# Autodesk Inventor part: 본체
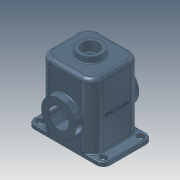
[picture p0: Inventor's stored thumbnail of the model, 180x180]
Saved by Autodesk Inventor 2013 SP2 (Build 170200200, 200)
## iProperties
Company: 한국ATC센터
Created: 2014-10
Part Number: 본체
Document SubType Name: Modeling
Designer: 한국ATC센터
Density: 2.71 g/cm^3
Material: 알루미늄 6061
Mass: 3285.46 g
Surface Area: 2358.48 cm^2
Volume: 1212.35 cm^3
Author: KYOUNG IL JANG
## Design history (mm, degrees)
sketch "스케치1"
  geometry: L1 (-70, 65)-(70, 65); L2 (70, 65)-(70, -65); L3 (70, -65)-(-70, -65); L4 (-70, -65)-(-70, 65); 3 further points
  constraints: 8 end point, 2 midpoint, 2 parallel, 1 horizontal, 1 horizontal alignment, 1 perpendicular, 1 vertical alignment
  dimensions: "d0" = 140 distance of L2.end L3.end; "d68" = 130 distance of L3.end L1.start
extrude "돌출1" new body sketch "스케치1" distance "d1" = 180; taper "d2" = 0 deg
fillet "모깎기1" dims "d3" = 20
feature "쉘1" dims "d4" = 10
sketch "스케치2"
  geometry: L1 (-70, 45)-(-70, -45) reference; L2 (-50, -65)-(-82, -65); L3 (-82, 65)-(-50, 65); L4 (-85, 57)-(-82, 57); L5 (-82, 41)-(-85, 41); L6 (-100, 47)-(-100, -47); A1 r 20 centre (-50, 45) between (-50, 65) and (-70, 45) reference; A2 r 20 centre (-50, -45) between (-70, -45) and (-50, -65) reference; A3 r 8 centre (-82, 49) between (-82, 41) and (-82, 57); A4 r 8 centre (-85, 49) between (-85, 57) and (-85, 41); A5 r 18 centre (-82, 47) between (-82, 65) and (-100, 47); A6 r 18 centre (-82, -47) between (-100, -47) and (-82, -65); 1 further point
  constraints: 10 end point, 9 tangent, 8 point on circle, 4 centre point, 2 parallel, 2 perpendicular, 1 equal radius
  dimensions: "d6" = 49 vertical distance of point (0, 0) A3.centre; "d8" = 16 distance between parallel lines of L4 L5; "d64" = 18 radius of A5; "d65" = 12 distance from line of A3.centre L1; "d66" = 30 distance between parallel lines of L6 L1; "d67" = 3 distance of A4.centre A3.centre
extrude "돌출2" join sketch "스케치2" distance "d9" = 10; taper "d10" = 0 deg
extrude "돌출3" cut sketch "스케치2" stored distance "d11" = 10; taper "d12" = 0 deg
sketch "스케치3"
  geometry: L1 (-65, 0)-(-65, 180) reference; L2 (-55, 0)-(-55, 170) reference; L3 (-83, 75)-(-51, 75); L4 (45, 0)-(-45, 0) reference; L5 (-83, 75)-(-83, 120.5); L6 (-83, 120.5)-(-55, 120.5); L7 (-55, 120.5)-(-51, 116.5); L8 (-51, 116.5)-(-51, 75); 2 further points
  constraints: 10 end point, 4 perpendicular, 1 point on line
  dimensions: "d13" = 75 distance between parallel lines of L3 L4; "d14" = 18 distance from line of L1 L3.start; "d15" = 4 distance from line of L3.end L2; "d16" = 91 diameter of L6 L3; "d17" = 135 deg angle of L7 L2
revolve "회전1" sketch "스케치3" stored, may be unused: angle "d18" = 90 deg
sketch "스케치4"
  geometry: C1 r 45.5 at (0, 0) reference; 2 further points
  constraints: 1 vertical alignment
  dimensions: "d19" = 35 distance of C1.centre point (0, 35)
hole "구멍1" sketch "스케치4" at (0, 35) diameter "d20" = 3.459; stored, may be unused: countersink angle "d24" = 90 deg, drill point angle "d26" = 118 deg; dims "d21" = 13, "d22" = 4, "d23" = 2, "d25" = 16
fillet "모깎기2" dims "d30" = 3
hole "구멍2" diameter "d33" = 52; stored, may be unused: countersink angle "d37" = 90 deg, drill point angle "d39" = 118 deg; dims "d31" = 10, "d32" = 10, "d34" = 13, "d35" = 4, "d36" = 2, "d38" = 16
sketch "스케치5"
  geometry: C1 r 31 at (0, 0); 1 further point
  constraints: 1 centre point, 1 coincident
  dimensions: "d40" = 62 diameter of C1
extrude "돌출4" join sketch "스케치5" distance "d41" = 15; taper "d42" = 0 deg
hole "구멍3" diameter "d45" = 43; stored, may be unused: countersink angle "d49" = 90 deg, drill point angle "d51" = 118 deg; dims "d43" = 10, "d44" = 10, "d46" = 13, "d47" = 4, "d48" = 2, "d50" = 16
fillet "모깎기3" dims "d52" = 3
fillet "모깎기4" dims "d53" = 3
chamfer "모따기1" distance "d55" = 1; stored, may be unused: second distance "d56" = 2, angle "d57" = 45 deg
sketch "스케치6"
  geometry: 2 further points
  constraints: 1 vertical alignment, 1 other
  dimensions: "d71" = 90 distance of point (0, 0) point (0, 90)
feature "엠보싱2" sketch "스케치6" dims "d0" = 140, "d68" = 130, "d72" = 1, "d73" = 0
fillet "모깎기6" dims "d74" = 10
sketch "스케치7"
  geometry: C1 r 15 at (0, 0); C2 r 21.5 at (0, 0) reference; C3 r 25 at (0, 0); 1 further point
  constraints: 2 centre point, 2 coincident
  dimensions: "d61" = 30 diameter of C1; "d75" = 50 diameter of C3
extrude "돌출5" join sketch "스케치7" distance "d62" = 10; taper "d63" = 0 deg
feature "면 이동1" dims "d76" = 1
fillet "모깎기7" dims "d77" = 3
node "솔리드1"
mirror "대칭1"
mirror "대칭2"
pattern_circular "원형 패턴1" dims angle "d28" = 360 deg
mirror "대칭3"
